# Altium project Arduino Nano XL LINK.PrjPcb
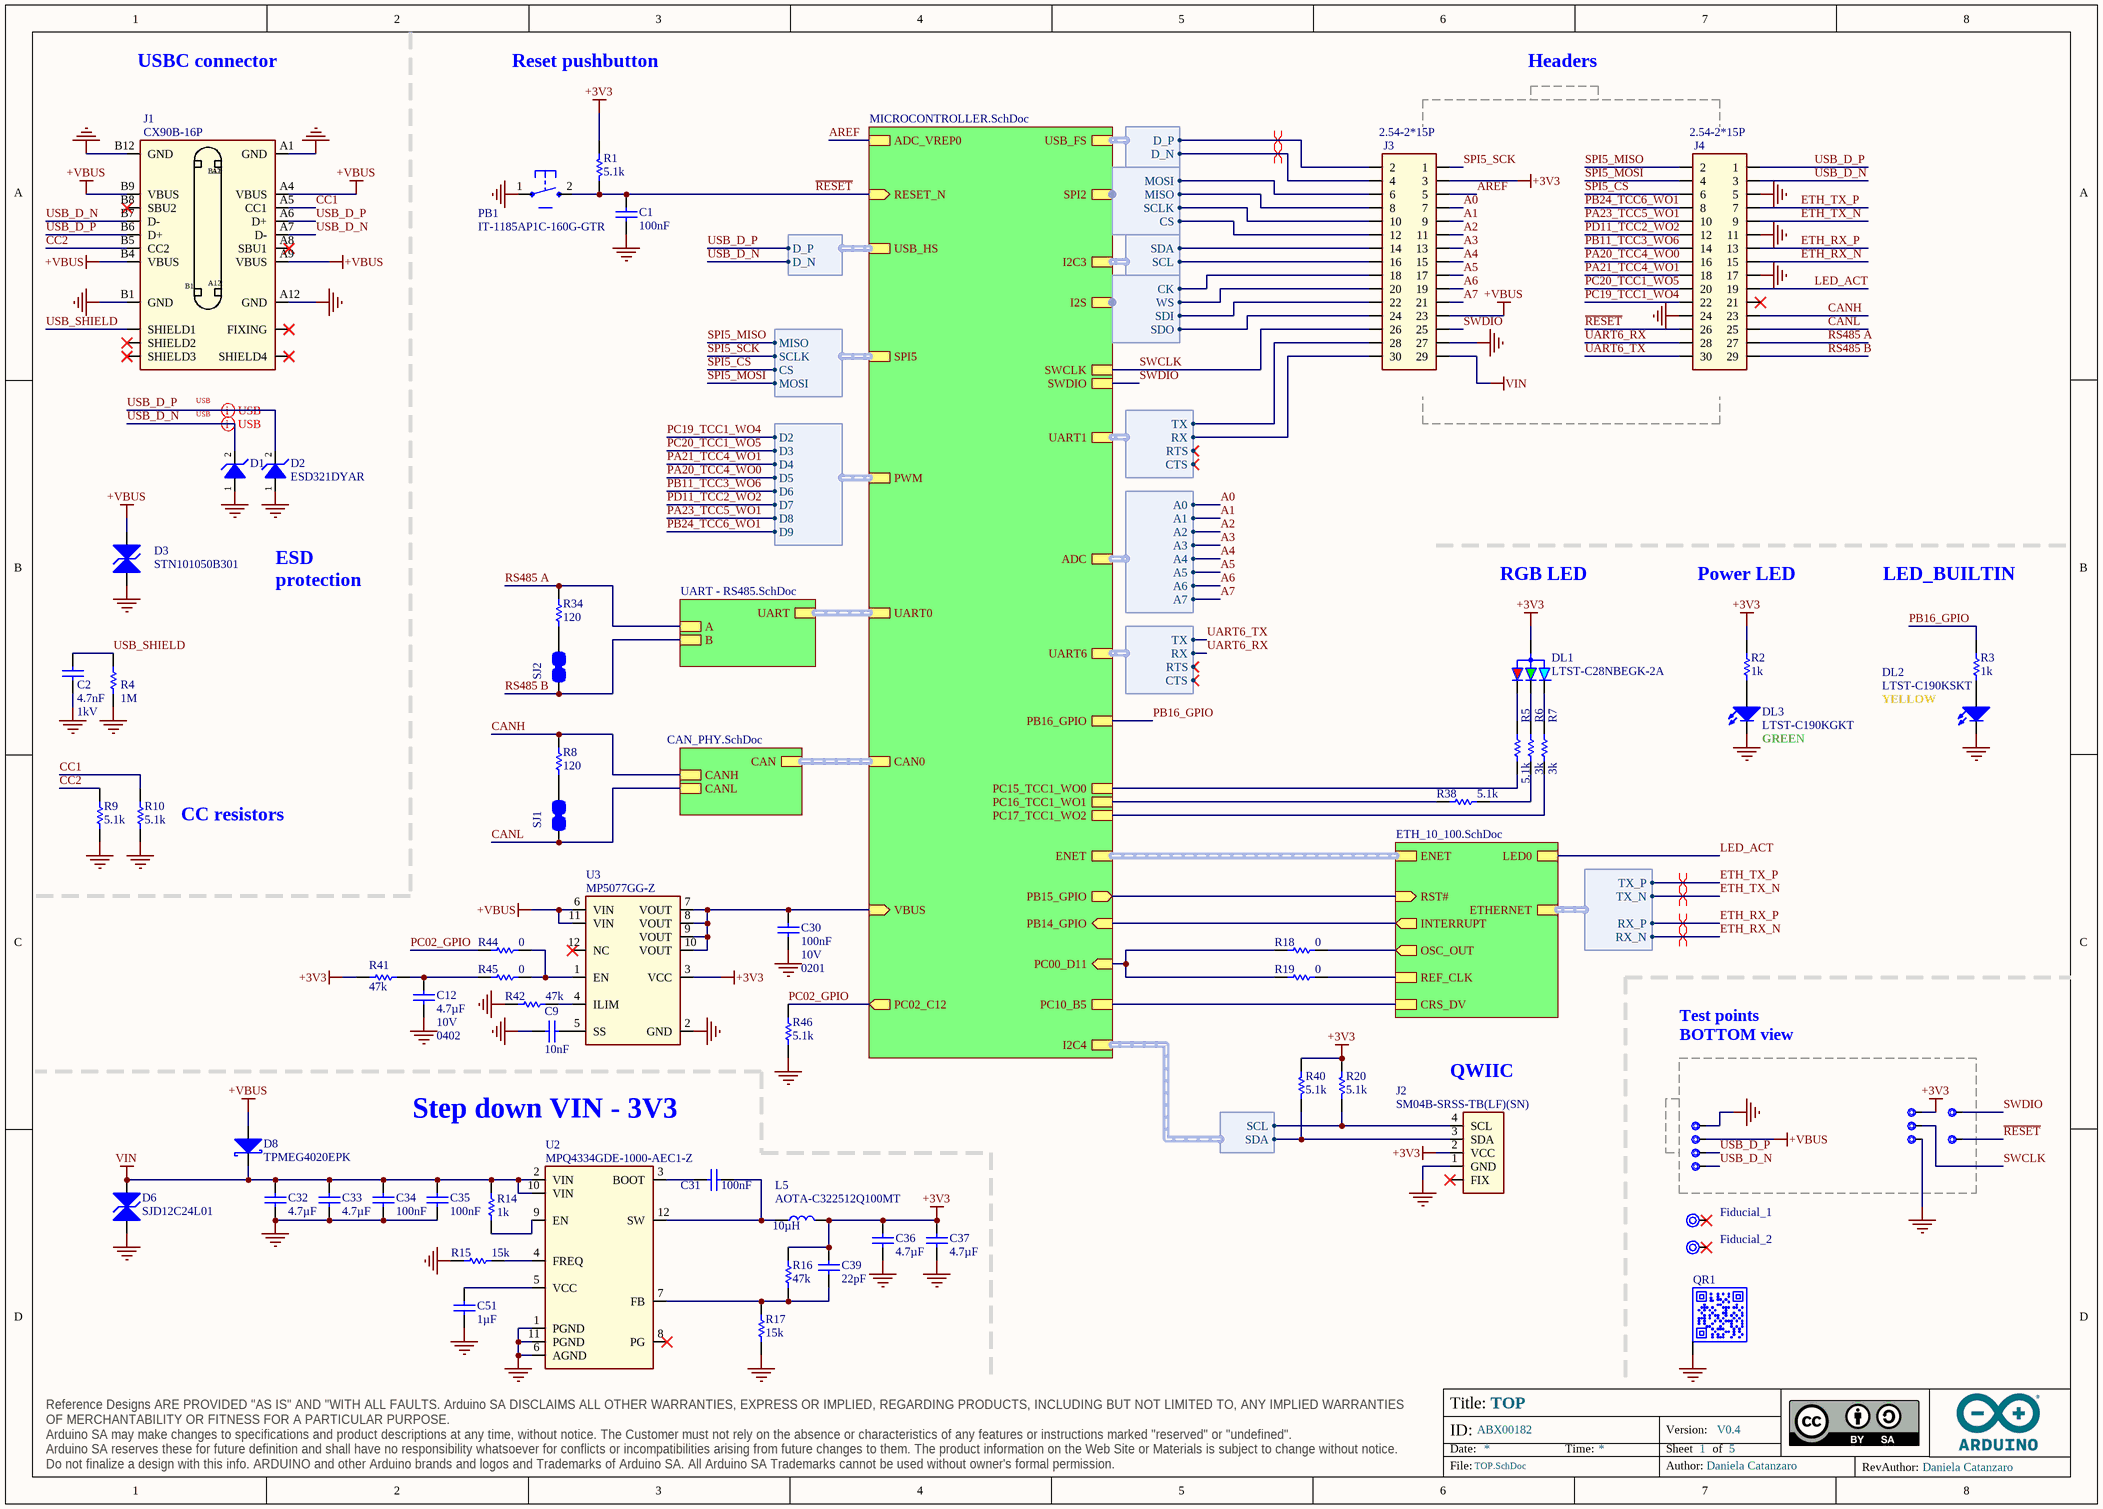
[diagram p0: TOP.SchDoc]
ASSEMBLY_BGA: X; ASSEMBLY_PRESSFIT: _; ASSEMBLY_SMD: X; ASSEMBLY_THT: X; BOARD_CODENAME: Arduino Nano Chandler; BOARD_INFO_AUTHOR: Daniela Catanzaro; BOARD_INFO_AUTHOR_REV: Daniela Catanzaro; BOARD_INFO_Er: _; BOARD_INFO_FLEX: _; BOARD_INFO_FR4: X; BOARD_INFO_FR4_HTG: _; BOARD_INFO_IPC1: _; BOARD_INFO_IPC2: X; BOARD_INFO_IPC3: _; BOARD_INFO_IPC_NA: X; BOARD_INFO_NUMBER_OF_LAYERS: 6; BOARD_INFO_PCB_SIZE: 43.18mm x 22.86mm; BOARD_INFO_POLYMIDE: _; BOARD_INFO_RIGID: X; BOARD_INFO_RIGID/FLEX: _; BOARD_INFO_TBD: _; BOARD_INFO_THICKNESS: 1.6mm; BOARD_OFFICIALNAME: Arduino Nano XL Link; DRILLS_BLIND: X; DRILLS_BURIED: _; DRILLS_COPPER_FILLING: _; DRILLS_FULL: X; DRILLS_LASER: _; DRILLS_PRESSFIT: _; DRILLS_RESIN_FILLING: _; DRILLS_SLOT: _; DRILLS_SOLDER_FILLING: X; FINISH_ADJUSTMENTS: _; FINISH_EDGE_PLATING: _; FINISH_ENIG: X; FINISH_HAL: _; FINISH_HAL_LF: _; FINISH_NI/AU: _; FINISH_SILK_BOTTOM: X; FINISH_SILK_COLOR: WHITE; FINISH_SILK_TOP: X; FINISH_SN/PB: _; FINISH_SOLDERMASK_BOTTOM: X; FINISH_SOLDERMASK_COLOR: BLUE; FINISH_SOLDERMASK_PEELABLE_BOTTOM: _; FINISH_SOLDERMASK_PEELABLE_COLOR: _; FINISH_SOLDERMASK_PEELABLE_TOP: _; FINISH_SOLDERMASK_TOP: X; FINISH_TABS: _; FINISH_TBD: _; INSULATION_MIN_INNER: 0.127mm; INSULATION_MIN_OUTER: 0.127mm; PANEL_MILLING: X; PANEL_NOT_REQUESTED: _; PANEL_NUMBER_OF_FIGURES: 16; PANEL_PROVIDED: X; PANEL_REQUESTED: _; PANEL_SCORING: X; PANEL_SIZE: 213mm x 132mm; PANEL_TABS: _; Revision: V0.4; SKU: ABX00182; TRACK_MIN_WIDTH_INNER: 0.127mm; TRACK_MIN_WIDTH_OUTER: 0.127mm; Version: V0.4; VIA_1: _; VIA_1_HOLE_MM: _; VIA_1_PAD_MM: _; VIA_2: _; VIA_2_HOLE_MM: _; VIA_2_PAD_MM: _; VIA_3: _; VIA_3_HOLE_MM: _; VIA_3_PAD_MM: _; VIA_4: _; VIA_4_HOLE_MM: _; VIA_4_PAD_MM: _; VIA_5: _; VIA_5_HOLE_MM: _; VIA_5_PAD_MM: _; VIA_BLIND_HOLE_MM: 0.1; VIA_BLIND_PAD_MM: 0.2; VIA_THROUGH: X; VIA_THROUGH_HOLE_MM: 0.2; VIA_THROUGH_PAD_MM: 0.4
5 sheets, 127 parts. Net scope: hierarchical (ports join the sheet entries above them; power ports are global).
Board files: PCB.PcbDoc, PANEL.PcbDoc
Sheets:
  TOP.SchDoc
    U_MICROCONTROLLER = MICROCONTROLLER.SchDoc
    U_CAN_PHY = CAN_PHY.SchDoc
    U_ETH_10_100 = ETH_10_100.SchDoc
    U_UART - RS485 = UART - RS485.SchDoc

## Sheet TOP.SchDoc: TOP
size A3; Author: Daniela Catanzaro; DocumentNumber: ABX00182; Revision: V0.1; SheetNumber: 1; SheetTotal: 5; RevAuthor: Daniela Catanzaro

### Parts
1  Test point 1.00mm  [TP-1.00MM]  (value not drawn)  (no BOM)
C1  value 100nF  [CAP-0201]  (hidden comment: CL03A104KP3NNNC)
C2  value 4.7nF  Voltage: 1kV  [CAP-0805]  (hidden comment: FV21X472K102ECG)
C9  value 10nF  [CAP-0201]  (hidden comment: CL03B103KP3NNND)
C12  value 4.7µF  Voltage: 10V  Case Code (Imperial): 0402  [CAP-0402]  (hidden comment: CC0402KRX5R6BB475)
C30  value 100nF  Voltage: 10V  Case Code (Imperial): 0201  [CAP-0201]  (hidden comment: CL03A104KP3NNNC)
C31  value 100nF  [CAP-0402]  (hidden comment: GRM155R61H104KE19D)
C32  value 4.7µF  [CAP-0603]  (hidden comment: GRM188R6YA475KE15D)
C33  value 4.7µF  [CAP-0603]  (hidden comment: GRM188R6YA475KE15D)
C34  value 100nF  [CAP-0402]  (hidden comment: GRM155R61H104KE19D)
C35  value 100nF  [CAP-0402]  (hidden comment: GRM155R61H104KE19D)
C36  value 4.7µF  [CAP-0402]  (hidden comment: CC0402KRX5R6BB475)
C37  value 4.7µF  [CAP-0402]  (hidden comment: CC0402KRX5R6BB475)
C39  value 22pF  [CAP-0201]  (hidden comment: CC0201JPNPO8BN220)
C51  value 1µF  [CAP-0402]  (hidden comment: C1005X5R1E105K050BC)
D1  ESD321DYAR  [ESD321DYAR]  (value not drawn)
D2  ESD321DYAR  [ESD321DYAR]
D3  STN101050B301  [X1-DFN1006-2]
D6  SJD12C24L01  [SOD123W_BIDIR]
D8  TPMEG4020EPK  [DFN1608-2 TPMEG4020EPK]
D+1  Test point 1.00mm  [TP-1.00MM]  (value not drawn)  (no BOM)
D-1  Test point 1.00mm  [TP-1.00MM]  (value not drawn)  (no BOM)
DL1  LTST-C28NBEGK-2A  [SMLP34RGB2W]
DL2  LTST-C190KSKT  [LEDC1608X80N-AK]
DL3  LTST-C190KGKT  [LEDC1608X80N-AK]
Fiducial_1  Fiducial mark 1mm with 2mm solder  [Fiducial mark 1mm with circle-Footprint-1]  (value not drawn)  (no BOM)
Fiducial_2  Fiducial mark 1mm with 2mm solder  [Fiducial mark 1mm with circle-Footprint-1]  (value not drawn)  (no BOM)
GND1  Test point 1.00mm  [TP-1.00MM]  (value not drawn)  (no BOM)
GND2  Test point 1.00mm  [TP-1.00MM]  (value not drawn)  (no BOM)
GPIO1  Test point 1.00mm  [TP-1.00MM]  (value not drawn)  (no BOM)
J1  CX90B-16P  [CX90B-16P-Footprint-1]
J2  SM04B-SRSS-TB(LF)(SN)  [SM04B-SRSS-TB(LF)(SN)-Footprint-1]
J3  2.54-2*15P  [PIN HEADER MALE 2.54mm VERT. 2x15POS]
J4  2.54-2*15P  [PIN HEADER MALE 2.54mm VERT. 2x15POS]
L5  AOTA-C322512Q100MT  Inductance: 10µH  [3225 IND]
NC1  Test point 1.00mm  [TP-1.00MM]  (value not drawn)  (no BOM)
NC2  Test point 1.00mm  [TP-1.00MM]  (value not drawn)  (no BOM)
PB1  IT-1185AP1C-160G-GTR  [C&K_PTS820_NO_HOLES-1]
QR1  QR CODE 4x4mm  [QR CODE 4x4mm]  (value not drawn)  (no BOM)
R1  value 5.1k  [RES-0201]  (hidden comment: RC0201FR-075K1L)
R2  value 1k  [RES-0201]  (hidden comment: RC0201FR-071KL)
R3  value 1k  [RES-0201]  (hidden comment: RC0201FR-071KL)
R4  value 1M  [RES-0402]  (hidden comment: CRCW04021M00FKED)
R5  value 5.1k  [RES-0201]  (hidden comment: RC0201FR-075K1L)
R6  value 3k  [RES-0201]  (hidden comment: RC0201FR-073KL)
R7  value 3k  [RES-0201]  (hidden comment: RC0201FR-073KL)
R8  value 120  [RES-0201]  (hidden comment: RC0201FR-07120RL)
R9  value 5.1k  [RES-0201]  (hidden comment: RC0201FR-075K1L)
R10  value 5.1k  [RES-0201]  (hidden comment: RC0201FR-075K1L)
R14  value 1k  [RES-0201]  (hidden comment: RC0201FR-071KL)
R15  value 15k  [RES-0201]  (hidden comment: CRCW020115K0FKED)
R16  value 47k  [RES-0201]  (hidden comment: CRCW020147K0FNEDAT)
R17  value 15k  [RES-0201]  (hidden comment: CRCW020115K0FKED)
R18  value 0  [RES-0201]  (hidden comment: CRCW02010000Z0ED)
R19  value 0  [RES-0201]  (hidden comment: CRCW02010000Z0ED)
R20  value 5.1k  [RES-0201]  (hidden comment: RC0201FR-075K1L)
R34  value 120  [RES-0201]  (hidden comment: RC0201FR-07120RL)
R38  value 5.1k  [RES-0201]  (hidden comment: RC0201FR-075K1L)
R40  value 5.1k  [RES-0201]  (hidden comment: RC0201FR-075K1L)
R41  value 47k  [RES-0201]  (hidden comment: CRCW020147K0FNEDAT)
R42  value 47k  [RES-0201]  (hidden comment: CRCW020147K0FNEDAT)
R44  value 0  [RES-0201]  (hidden comment: CRCW02010000Z0ED)
R45  value 0  [RES-0201]  (hidden comment: CRCW02010000Z0ED)
R46  value 5.1k  [RES-0201]  (hidden comment: RC0201FR-075K1L)
SJ1  SOLDER JUMPER CLOSED 0603  [SJ 0603 CLOSED]  (value not drawn)  (no BOM)
SJ2  SOLDER JUMPER CLOSED 0603  [SJ 0603 CLOSED]  (value not drawn)  (no BOM)
TP_VUSB1  Test point 1.00mm  [TP-1.00MM]  (value not drawn)  (no BOM)
U2  MPQ4334GDE-1000-AEC1-Z  [MPQ4334GDE-1000-AEC1-Z]
U3  MP5077GG-Z  [MPS QFN12 2x2mm pitch 0.4mm]

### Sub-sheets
U_CAN_PHY = CAN_PHY.SchDoc: CAN (harness CAN_3V3), CANH, CANL
U_ETH_10_100 = ETH_10_100.SchDoc: LED0, ETHERNET (harness ETH), ENET (harness ENET), RST# (in), INTERRUPT (out), OSC_OUT (out), REF_CLK, CRS_DV
U_MICROCONTROLLER = MICROCONTROLLER.SchDoc: RESET_N (in), USB_HS (harness USB), SPI5 (harness SPI), ENET (harness ENET), CAN0 (harness CAN_3V3), SPI2 (harness SPI), UART1 (harness UART), I2S (harness I2S), ADC (harness ANALOG), ADC_VREP0, PWM (harness PWM), I2C3 (harness I2C), USB_FS (harness USB), UART6 (harness UART), SWDIO, SWCLK, PB14_GPIO (in), PB15_GPIO (out), PC15_TCC1_WO0, PC16_TCC1_WO1, PC17_TCC1_WO2, PB16_GPIO, PC00_D11 (in), PC10_B5, UART0 (harness UART), I2C4 (harness I2C), VBUS (in), PC02_C12 (out)
U_UART - RS485 = UART - RS485.SchDoc: UART (harness UART), A, B

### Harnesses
ANALOG: A0, A1, A2, A3, A4, A5, A6, A7
USB: D_P, D_N
I2C: SDA, SCL
SPI: CS, MOSI, SCLK, MISO
UART: CTS, RX, RTS, TX
I2S: SDO, WS, SDI, CK
PWM: D2, D3, D4, D5, D6, D7, D8, D9
ETH: TX_N, TX_P, RX_N, RX_P

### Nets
+3V3: 1.X C36.2 C37.2 C39.2 DL1.1(ANODE) J2.2(VCC) J3.3 L5.2 R1.2 R2.2 R16.2 R20.2 R40.2 R41.2 U3.3(VCC)
+VBUS: D3.1(A1) D8.A J1.A4(VBUS) J1.A9(VBUS) J1.B4(VBUS) J1.B9(VBUS) J3.23 TP_VUSB1.X U3.6(VIN) U3.11(VIN)
GND: C1.1 C2.1 C9.2 C12.1 C30.1 C32.1 C33.1 C34.1 C35.1 C36.1 C37.1 C51.1 D1.1 D2.1 D3.2(A2) D6.1(A1) DL2.C DL3.C GND1.X GND2.X J1.A1(GND) J1.A12(GND) J1.B1(GND) J1.B12(GND) J2.1(GND) J3.27 J4.5 J4.11 J4.17 J4.24 PB1.1 QR1.PAD R4.1 R9.1 R10.1 R15.2 R17.1 R42.2 R46.2 U2.1(PGND) U2.6(AGND) U2.11(PGND) U3.2(GND)
VIN: C32.2 C33.2 C34.2 C35.2 D6.2(A2) D8.C J3.29 R14.1 U2.2(VIN) U2.10(VIN)
A0: J3.7 ; sheet U_MICROCONTROLLER/ADC.A0
A1: J3.9 ; sheet U_MICROCONTROLLER/ADC.A1
A2: J3.11 ; sheet U_MICROCONTROLLER/ADC.A2
A3: J3.13 ; sheet U_MICROCONTROLLER/ADC.A3
A4: J3.15 ; sheet U_MICROCONTROLLER/ADC.A4
A5: J3.17 ; sheet U_MICROCONTROLLER/ADC.A5
A6: J3.19 ; sheet U_MICROCONTROLLER/ADC.A6
A7: J3.21 ; sheet U_MICROCONTROLLER/ADC.A7
AREF: J3.5 ; sheet U_MICROCONTROLLER/ADC_VREP0
CANH: J4.23 R8.2 ; sheet U_CAN_PHY/CANH
CANL: J4.25 SJ1.1 ; sheet U_CAN_PHY/CANL
CC1: J1.A5(CC1) R10.2  [project net CC1_1]
CC2: J1.B5(CC2) R9.2  [project net CC2_1]
ETH_RX_N: J4.15 ; sheet U_ETH_10_100/ETHERNET.RX_N
ETH_RX_P: J4.13 ; sheet U_ETH_10_100/ETHERNET.RX_P
ETH_TX_N: J4.9 ; sheet U_ETH_10_100/ETHERNET.TX_N
ETH_TX_P: J4.7 ; sheet U_ETH_10_100/ETHERNET.TX_P
INTRP: sheet U_MICROCONTROLLER/PB14_GPIO, sheet U_ETH_10_100/INTERRUPT
LED_ACT: J4.19 ; sheet U_ETH_10_100/LED0  [project net ANEN_SPEED]
PA20_TCC4_WO0: J4.16 ; sheet U_MICROCONTROLLER/PWM.D5
PA21_TCC4_WO1: J4.18 ; sheet U_MICROCONTROLLER/PWM.D4
PA23_TCC5_WO1: J4.10 ; sheet U_MICROCONTROLLER/PWM.D8
PB11_TCC3_WO6: J4.14 ; sheet U_MICROCONTROLLER/PWM.D6
PB16_GPIO: R3.2 ; sheet U_MICROCONTROLLER/PB16_GPIO
PB24_TCC6_WO1: J4.8 ; sheet U_MICROCONTROLLER/PWM.D9
PC02_GPIO: R44.2 R46.1 ; sheet U_MICROCONTROLLER/PC02_C12
PC19_TCC1_WO4: J4.22 ; sheet U_MICROCONTROLLER/PWM.D2
PC20_TCC1_WO5: J4.20 ; sheet U_MICROCONTROLLER/PWM.D3
PD11_TCC2_WO2: J4.12 ; sheet U_MICROCONTROLLER/PWM.D7
PHYAD_1:0: sheet U_MICROCONTROLLER/PC10_B5, sheet U_ETH_10_100/CRS_DV
PHYAD_2: R19.1 ; sheet U_ETH_10_100/REF_CLK
~{RESET}: C1.2 J4.26 NC2.X PB1.2 R1.1 ; sheet U_MICROCONTROLLER/RESET_N
RS485 A: J4.27 R34.2 ; sheet U_UART - RS485/A
RS485 B: J4.29 SJ2.1 ; sheet U_UART - RS485/B
RST#: sheet U_MICROCONTROLLER/PB15_GPIO, sheet U_ETH_10_100/RST#
SPI2_CS: J3.12 ; sheet U_MICROCONTROLLER/SPI2.CS
SPI5_CS: J4.6 ; sheet U_MICROCONTROLLER/SPI5.CS
SPI5_MISO: J4.2 ; sheet U_MICROCONTROLLER/SPI5.MISO
SPI5_MOSI: J4.4 ; sheet U_MICROCONTROLLER/SPI5.MOSI
SPI5_SCK: J3.1 ; sheet U_MICROCONTROLLER/SPI5.SCLK
SWCLK: GPIO1.X J3.26 ; sheet U_MICROCONTROLLER/SWCLK
SWDIO: J3.25 NC1.X ; sheet U_MICROCONTROLLER/SWDIO
UART6_RX: J4.28 ; sheet U_MICROCONTROLLER/UART6.RX
UART6_TX: J4.30 ; sheet U_MICROCONTROLLER/UART6.TX
USB_D_N: D1.2 D-1.X J1.A7(D-) J1.B7(D-) J4.3 ; sheet U_MICROCONTROLLER/USB_HS.D_N
USB_D_P: D2.2 D+1.X J1.A6(D+) J1.B6(D+) J4.1 ; sheet U_MICROCONTROLLER/USB_HS.D_P
USB_SHIELD: C2.2 J1.SHIELD1 R4.2  [project net USB_SHIELD_1]
USBFS_D_N: J3.4 ; sheet U_MICROCONTROLLER/USB_FS.D_N
USBFS_D_P: J3.2 ; sheet U_MICROCONTROLLER/USB_FS.D_P
NetC9_1: C9.1 U3.5(SS)
NetC12_2: C12.2 R41.1 R45.2
NetC30_2: C30.2 U3.7(VOUT) U3.8(VOUT) U3.9(VOUT) U3.10(VOUT) ; sheet U_MICROCONTROLLER/VBUS
NetC31_1: C31.1 L5.1 U2.12(SW)
NetC31_2: C31.2 U2.3(BOOT)
NetC39_1: C39.1 R16.1 R17.2 U2.7(FB)
NetC51_2: C51.2 U2.5(VCC)
NetDL1_2: DL1.2(RED_C) R5.2
NetDL1_3: DL1.3(BLUE_C) R7.2
NetDL1_4: DL1.4(GREEN_C) R6.2
NetDL2_A: DL2.A R3.1
NetDL3_A: DL3.A R2.1
NetJ2_3: J2.3(SDA) R40.1 ; sheet U_MICROCONTROLLER/I2C4.SDA
NetJ2_4: J2.4(SCL) R20.1 ; sheet U_MICROCONTROLLER/I2C4.SCL
NetJ3_6: J3.6 ; sheet U_MICROCONTROLLER/SPI2.MOSI
NetJ3_8: J3.8 ; sheet U_MICROCONTROLLER/SPI2.MISO
NetJ3_10: J3.10 ; sheet U_MICROCONTROLLER/SPI2.SCLK
NetJ3_14: J3.14 ; sheet U_MICROCONTROLLER/I2C3.SDA
NetJ3_16: J3.16 ; sheet U_MICROCONTROLLER/I2C3.SCL
NetJ3_18: J3.18 ; sheet U_MICROCONTROLLER/I2S.CK
NetJ3_20: J3.20 ; sheet U_MICROCONTROLLER/I2S.WS
NetJ3_22: J3.22 ; sheet U_MICROCONTROLLER/I2S.SDI
NetJ3_24: J3.24 ; sheet U_MICROCONTROLLER/I2S.SDO
NetJ3_28: J3.28 ; sheet U_MICROCONTROLLER/UART1.TX
NetJ3_30: J3.30 ; sheet U_MICROCONTROLLER/UART1.RX
NetR5_1: R5.1 ; sheet U_MICROCONTROLLER/PC15_TCC1_WO0
NetR6_1: R6.1 R38.1
NetR7_1: R7.1 ; sheet U_MICROCONTROLLER/PC17_TCC1_WO2
NetR8_1: R8.1 SJ1.2
NetR14_2: R14.2 U2.9(EN)
NetR15_1: R15.1 U2.4(FREQ)
NetR18_1: R18.1 ; sheet U_ETH_10_100/OSC_OUT
NetR18_2: R18.2 R19.2 ; sheet U_MICROCONTROLLER/PC00_D11
NetR34_1: R34.1 SJ2.2
NetR38_2: R38.2 ; sheet U_MICROCONTROLLER/PC16_TCC1_WO1
NetR42_1: R42.1 U3.4(ILIM)
NetR44_1: R44.1 R45.1 U3.1(EN)

Not connected (* = marked no-connect by the designer): Fiducial_1 1*; Fiducial_2 1*; J1 A8(SBU1)* B8(SBU2)* FIXING* SHIELD2* SHIELD3* SHIELD4*; J2 FIX*; J4 21*; U2 8(PG)*; U3 12(NC)*

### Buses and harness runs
harness sheet U_CAN_PHY/CAN = sheet U_MICROCONTROLLER/CAN0
harness sheet U_ETH_10_100/ENET = sheet U_MICROCONTROLLER/ENET
harness sheet U_MICROCONTROLLER/UART0 = sheet U_UART - RS485/UART

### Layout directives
differential pair; differential pair class USB: USB_D_N, USB_D_P
differential pair; differential pair class USBC_FS: USBFS_D_N, USBFS_D_P
differential pair; differential pair class ETH: ETH_RX_N, ETH_RX_P, ETH_TX_N, ETH_TX_P

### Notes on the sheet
- USBC connector
- Reset pushbutton
- Headers
- RGB LED
- Power LED
- LED_BUILTIN
- ESD
  protection
- YELLOW
- (near DL3) GREEN
- (near R10) CC resistors
- Test points BOTTOM view
- Step down VIN - 3V3
- (near J2) QWIIC

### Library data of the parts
1 D+1 D-1 GND1 GND2 GPIO1 NC1 NC2 TP_VUSB1 = UT0013-A.6: Manufacturer: This is not a component
C1 C30 = C0113-A.8: CAP CHIP 0201 100nF 10% 10V X5R; Manufacturer: Samsung Electro-Mechanics; Code Arduino: C0113
C2 = C0059-A.16: CAP CHIP 0805 4.7nF 10% 1000V X7R; Manufacturer: PSA Shenzen; Code Arduino: 0689
C9 = C0205-A.3: CAP CHIP 0201 10nF 10% 10V X7R; Manufacturer: Samsung; Code Arduino: C0205
C12 C36 C37 = C0195-A.3: CAP CHIP 0402 4.7uF 10% 10V X5R; Manufacturer: YAGEO; Code Arduino: C0195
C31 C34 C35 = C0015-A.16: CAP CHIP 0402 100nF 10% 50V X5R; Manufacturer: Murata; Code Arduino: A5141
C32 C33 = C0055-A.16: CAP CHIP 0603 4.7uF 10% 35V X5R; Manufacturer: Murata; Code Arduino: 0458
C39 = C0115-A.8: CAP CHIP 0201 22pF 5% 25V C0G; Manufacturer: Yageo; Code Arduino: C0115
C51 = C0177-A.4: CAP CHIP 0402 1uF 10% 25V X5R; Manufacturer: TDK; Code Arduino: C0177
D1 D2 = P0022-5: TVS 1CH, 30kV, USB 2.0 ETH 10/100/1000, 0-3.6V, 0.9pF, IEC61000-4-5 peak current 80A surge 40W 6A, DC breakdown min 4.5V, SOD523 1.6x0.8mm; Manufacturer: Texas Instruments; Code Arduino: P0022
D3 = D0095-2: TVS BIDIRECTIONAL SMD Vr = 5V, Vbr min =  5.5V, 300W, DFN1006-2; Manufacturer: Eaton Electronics; Ireverse max: 1µA; Vforward max: 0V; Code Arduino: D0095
D6 = D0106-4: TVS BIDIRECTIONAL SMD Vr = 24V, Vbr min =  26.7V, Vcl = 38.9V, Ileakage = 1uA, 200W, SOD-123; Manufacturer: YAGEO; Code Arduino: D0106; V(BR) min: 26.7; V(RWM) max: 24; Ireverse max: 1µA; Vforward max: 0V
D8 = D0105-1: DIODE SCHOTTKY SMD 2A 40V DFN1608-2; Manufacturer: TECH PUBLIC; Code Arduino: D0105; Vforward max: 550mV; Power max: 415mW
DL1 = L0014-A.13: LED RGB DIFFUSED PICOLED SMD; Manufacturer: Liteon; Code Arduino: A5469; Lens Style: Rectangular; Forward Voltage: 3V; Luminous Intensity: 45mcd; Lens Color: White; Dominant Wavelength: 470nm; Forward Current: 20mA; Test Current: 5mA
DL2 = L0008-A.6: LED SMD 0603 GIA588   8mcd 120^; Manufacturer: Liteon; Code Arduino: 2243
DL3 = L0009-A.6: LED SMD 0603 GREEN/568 15mcd 120^; Manufacturer: Liteon; Code Arduino: 2204
Fiducial_1 Fiducial_2 = UT0024-A.6
J1 = J0272-A.3: CONN RCPT USB3.1 TYPEC 16POS SMD; Manufacturer: Hirose; Code Arduino: J0272
J2 = J0005-A.3: CONN JST SH 1mm 4POS HORIZONTAL TIN QWIIC; Code Arduino: J0005
J3 J4 = J0592-A.5: HEADER TH 2.54mm VERT. 2x015POS MALE 6mm pin height; Manufacturer: BOOMELE; Code Arduino: J0592
L5 = I0131-A.1: IND FIXED 10uH 210mR Idc:1.8A Isat:2.3A 3.2 x 2.5 x 1.2mm; Manufacturer: ABRACON; Resonant frequency: 1MHz; Tolerance: 20%; ISAT: 2.3A; Code Arduino: I0131; IRMS: 1.8A
PB1 = B0001-A.7: PUSHBUTTON WHITE NO ANCHORS; Manufacturer: Switronic; Code Arduino: 0173
QR1 = QR-0001-A.5: QR CODE 4x4mm on layer 34 (This is not a component); Code Arduino: QRCODE_4x4mm
R1 R5 R20 R38 R40 R46 = R0169-A.26: RES CHIP 0201 5k1 1% 1/20W; Manufacturer: Yageo; Code Arduino: R0169; Power: 50mW; Temperature coefficient: 200ppm
R2 R3 = R0195-A.23: RES CHIP 0201 1k 1% 1/20W; Manufacturer: Yageo; Code Arduino: R0195; Power: 50mW; Temperature coefficient: 200ppm
R4 = R0058-A.25: RES CHIP 0402 1M 1% 1/16W; Manufacturer: Vishay; Power: 62.5mW; Code Arduino: 0139; Temperature coefficient: 100ppm
R6 R7 = R0416-A.2: RES CHIP 0201 3k 1% 1/20W; Manufacturer: YAGEO; Code Arduino: R0416; Power: 50mW; Temperature Coefficient: 200ppm
R8 R34 = R0306-A.2: RES CHIP 0201 120R 1% 1/20W; Manufacturer: YAGEO; Code Arduino: R0306; Power: 50mW; Temperature Coefficient: 200ppm
R9 R10 = R0169-A.26: RES CHIP 0201 5k1 1% 1/20W; Manufacturer: Yageo; Power: 50mW; Code Arduino: R0169; Temperature coefficient: 200ppm
R14 = R0195-A.23: RES CHIP 0201 1k 1% 1/20W; Manufacturer: Yageo; Temperature coefficient: 200ppm; Power: 50mW; Code Arduino: R0195
R15 R17 = R0213-A.19: RES CHIP 0201 15k 1% 1/20W; Manufacturer: Vishay; Code Arduino: R0213; Power: 50mW; Temperature coefficient: 100ppm
R16 R41 R42 = R0413-A.2: RES CHIP 0201 47k 1% 1/20W; Manufacturer: Vishay; Code Arduino: R0413; Power: 50mW; Temperature Coefficient: 200ppm
R18 R19 R44 R45 = R0140-A.22: RES CHIP 0201 0R; Manufacturer: Vishay; Temperature coefficient: 0ppm; Code Arduino: R0140; Power: 50mW; Tolerance: 0%
SJ1 SJ2 = UT0039-A.4: Code Arduino: This is not a component
U2 = U0537-A.2: IC BUCK Vin 36V, Vout ADJ, Iout 1A, synchronous 65mR/45mR, 2.5MHz, QFN12 2x3mm; Manufacturer: MPS; Code Arduino: U0537
U3 = U0512-A.2: IC Load Switch Vload 0.5V to 5.5V, 10mR at 5V, max 7A, programmable overcurrent limit, linear ramp control, logic ON 1.7V, VCC 3V to 5.5V, -40 to 125°C, QFN12 2x2mm; Manufacturer: MPS; Code Arduino: U0512

## Sheet MICROCONTROLLER.SchDoc: MICROCONTROLLER
size A3; SheetNumber: 2; SheetTotal: 5
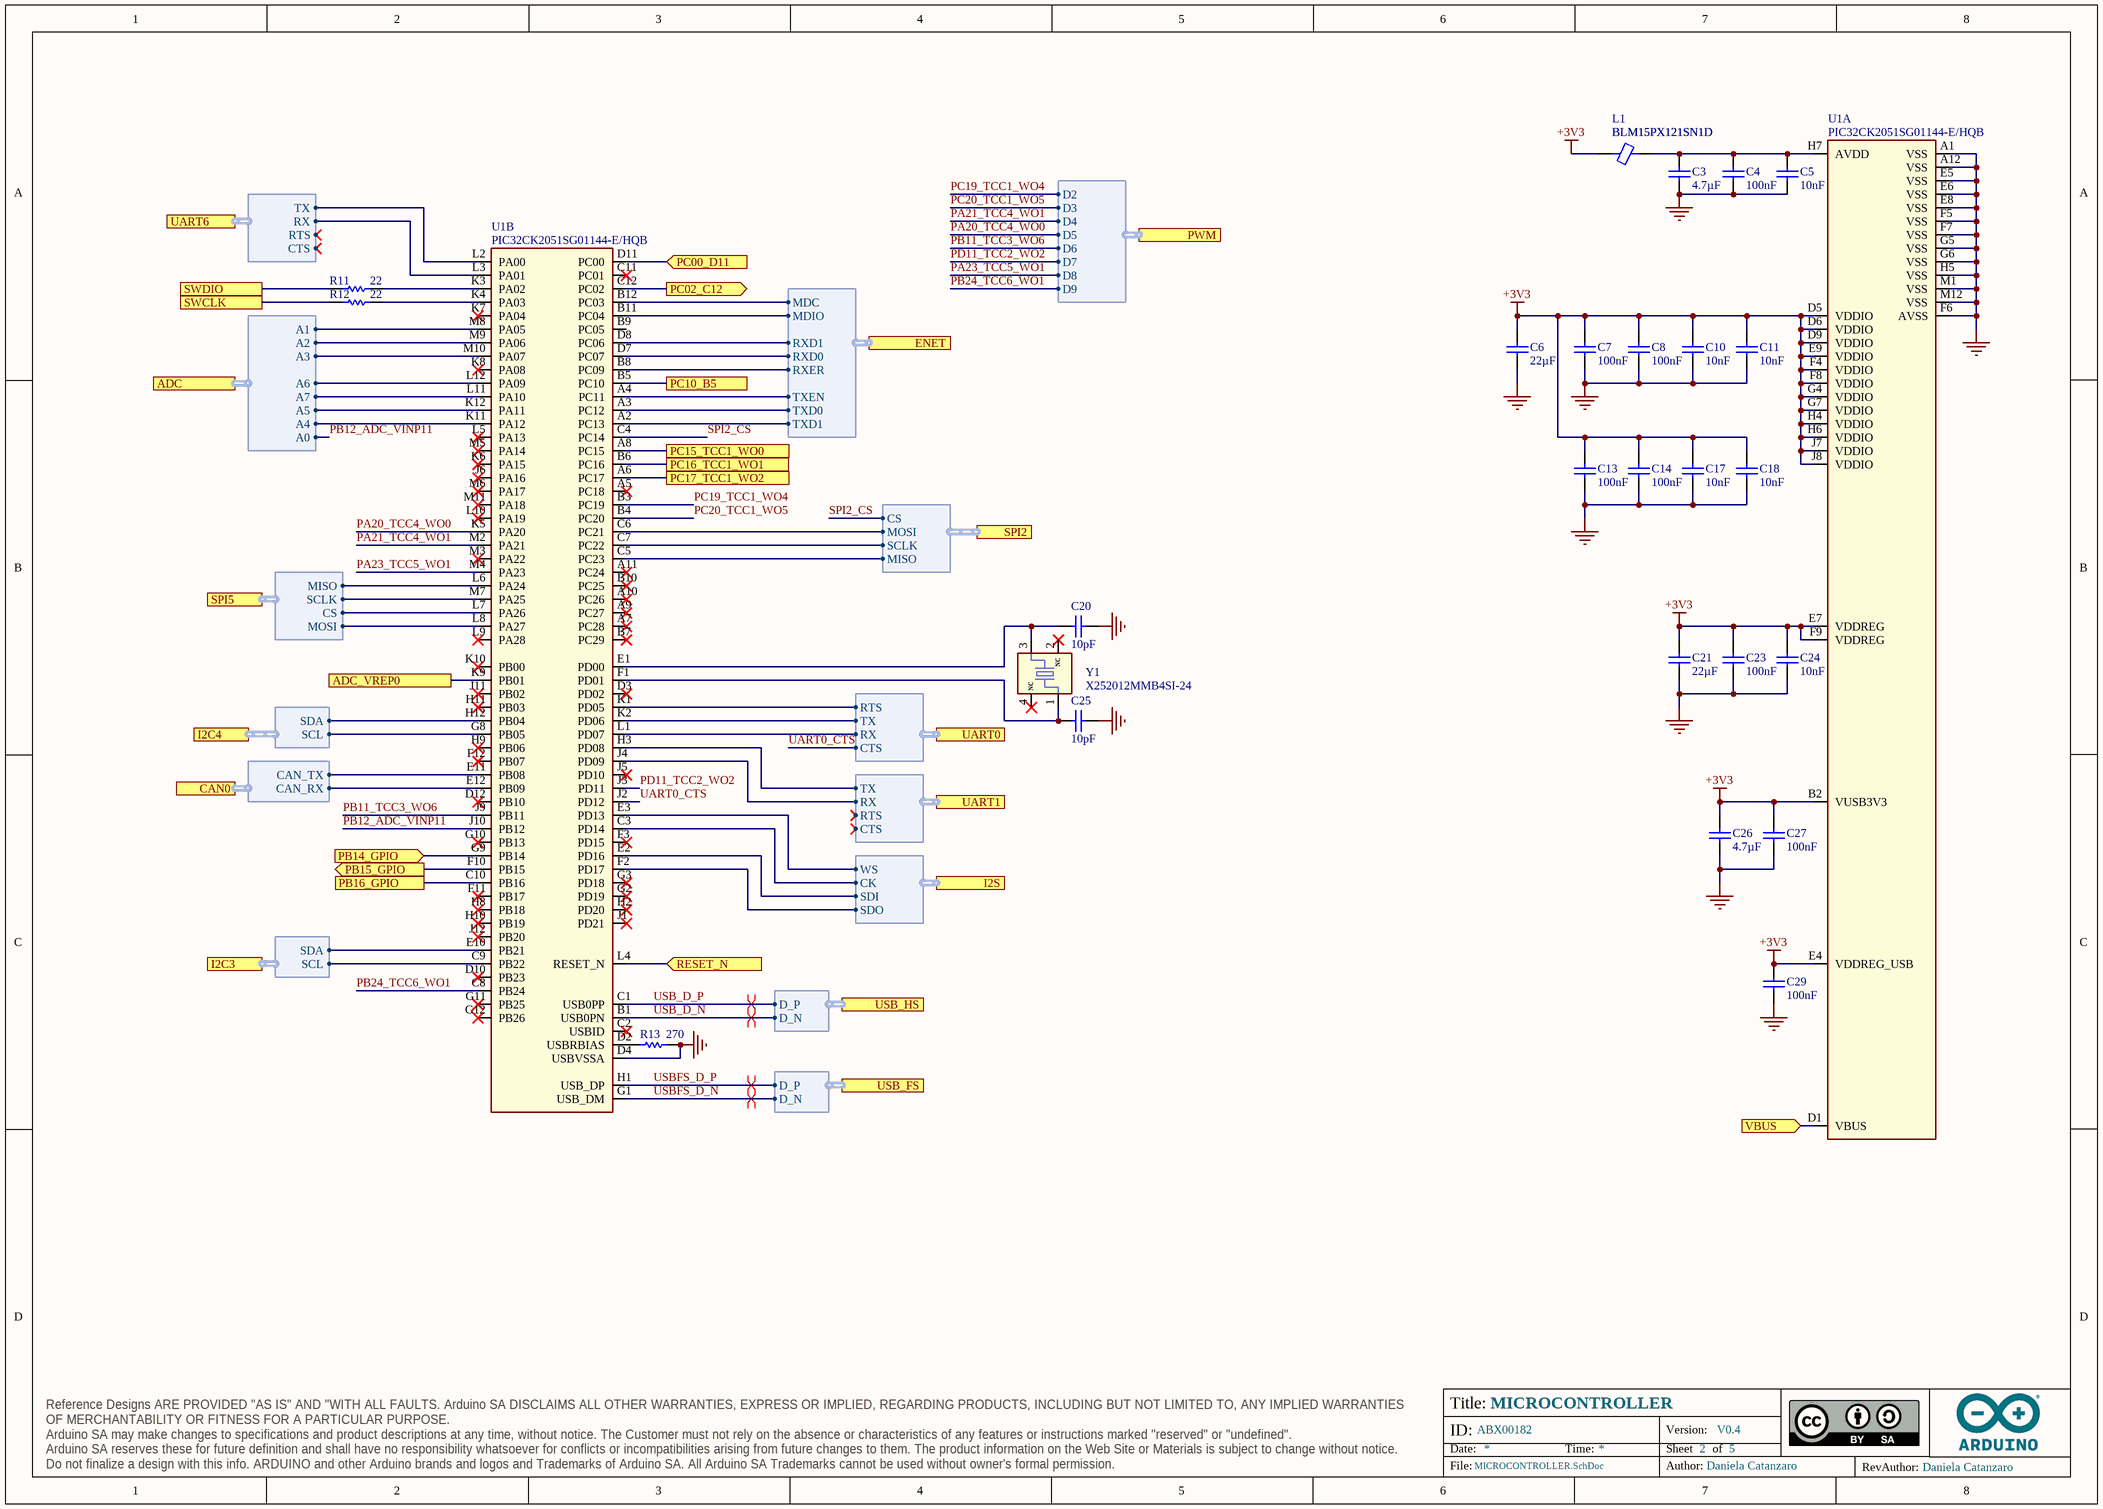
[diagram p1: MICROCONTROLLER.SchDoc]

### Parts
C3  value 4.7µF  [CAP-0402]  (hidden comment: CC0402KRX5R6BB475)
C4  value 100nF  [CAP-0201]  (hidden comment: CL03A104KP3NNNC)
C5  value 10nF  [CAP-0201]  (hidden comment: CL03B103KP3NNND)
C6  value 22µF  [CAP-0402]  (hidden comment: GRM158R60J226ME01D)
C7  value 100nF  [CAP-0201]  (hidden comment: CL03A104KP3NNNC)
C8  value 100nF  [CAP-0201]  (hidden comment: CL03A104KP3NNNC)
C10  value 10nF  [CAP-0201]  (hidden comment: CL03B103KP3NNND)
C11  value 10nF  [CAP-0201]  (hidden comment: CL03B103KP3NNND)
C13  value 100nF  [CAP-0201]  (hidden comment: CL03A104KP3NNNC)
C14  value 100nF  [CAP-0201]  (hidden comment: CL03A104KP3NNNC)
C17  value 10nF  [CAP-0201]  (hidden comment: CL03B103KP3NNND)
C18  value 10nF  [CAP-0201]  (hidden comment: CL03B103KP3NNND)
C20  value 10pF  [CAP-0201]  (hidden comment: CC0201GRNPO9BN100)
C21  value 22µF  [CAP-0402]  (hidden comment: GRM158R60J226ME01D)
C23  value 100nF  [CAP-0201]  (hidden comment: CL03A104KP3NNNC)
C24  value 10nF  [CAP-0201]  (hidden comment: CL03B103KP3NNND)
C25  value 10pF  [CAP-0201]  (hidden comment: CC0201GRNPO9BN100)
C26  value 4.7µF  [CAP-0402]  (hidden comment: CC0402KRX5R6BB475)
C27  value 100nF  [CAP-0201]  (hidden comment: CL03A104KP3NNNC)
C29  value 100nF  [CAP-0201]  (hidden comment: CL03A104KP3NNNC)
L1  BLM15PX121SN1D  [L-0402]
R11  value 22  [RES-0201]  (hidden comment: RC0201FR-0722RL)
R12  value 22  [RES-0201]  (hidden comment: RC0201FR-0722RL)
R13  value 270  [RES-0201]  (hidden comment: RC0201FR-07270RL)
U1  PIC32CK2051SG01144-E/HQB  [TFBGA-144]  (parts A,B of 2)
Y1  X252012MMB4SI-24  [CRYSTAL_2.5x2mm]

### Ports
ADC (harness ANALOG), ADC_VREP0, CAN0 (harness CAN_3V3), ENET (harness ENET), I2C3 (harness I2C), I2C4 (harness I2C), I2S (harness I2S), PB14_GPIO (in), PB15_GPIO (out), PB16_GPIO, PC00_D11 (in), PC02_C12 (out), PC10_B5, PC15_TCC1_WO0, PC16_TCC1_WO1, PC17_TCC1_WO2, PWM (harness PWM), RESET_N (in), SPI2 (harness SPI), SPI5 (harness SPI), SWCLK, SWDIO, UART0 (harness UART), UART1 (harness UART), UART6 (harness UART), USB_FS (harness USB), USB_HS (harness USB), VBUS (in)

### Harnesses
USB: D_P, D_N
SPI: CS, MOSI, SCLK, MISO
ENET: TXEN, TXD0, TXD1, RXD0, RXD1, MDC, MDIO, RXER
CAN_3V3: CAN_TX, CAN_RX
UART: CTS, RX, RTS, TX
I2C: SDA, SCL
I2S: SDO, WS, SDI, CK
ANALOG: A0, A1, A2, A3, A6, A7, A5, A4
PWM: D2, D3, D4, D5, D6, D7, D8, D9

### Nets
+3V3: C6.2 C7.2 C8.2 C10.2 C11.2 C13.2 C14.2 C17.2 C18.2 C21.2 C23.2 C24.2 C26.2 C27.2 C29.2 L1.1 U1.B2(VUSB3V3) U1.D5(VDDIO) U1.D6(VDDIO) U1.D9(VDDIO) U1.E4(VDDREG_USB) U1.E7(VDDREG) U1.E9(VDDIO) U1.F4(VDDIO) U1.F8(VDDIO) U1.F9(VDDREG) U1.G4(VDDIO) U1.G7(VDDIO) U1.H4(VDDIO) U1.H6(VDDIO) U1.J7(VDDIO) U1.J8(VDDIO)
GND: C3.1 C4.1 C5.1 C6.1 C7.1 C8.1 C10.1 C11.1 C13.1 C14.1 C17.1 C18.1 C20.2 C21.1 C23.1 C24.1 C25.2 C26.1 C27.1 C29.1 R13.2 U1.A1(VSS) U1.A12(VSS) U1.D4(USBVSSA) U1.E5(VSS) U1.E6(VSS) U1.E8(VSS) U1.F5(VSS) U1.F6(AVSS) U1.F7(VSS) U1.G5(VSS) U1.G6(VSS) U1.H5(VSS) U1.M1(VSS) U1.M12(VSS)
A1: U1.M8(PA05) ; port ADC.A1
A2: U1.M9(PA06) ; port ADC.A2
A3: U1.M10(PA07) ; port ADC.A3
A4: U1.K11(PA12) ; port ADC.A4
A5: U1.K12(PA11) ; port ADC.A5
A6: U1.L12(PA09) ; port ADC.A6
A7: U1.L11(PA10) ; port ADC.A7
AREF: U1.K9(PB01) ; port ADC_VREP0
INTRP: U1.G9(PB14) ; port PB14_GPIO
MDC: U1.B12(PC03) ; port ENET.MDC
MDIO: U1.B11(PC04) ; port ENET.MDIO
PA20_TCC4_WO0: U1.K5(PA20) ; port PWM.D5
PA21_TCC4_WO1: U1.M2(PA21) ; port PWM.D4
PA23_TCC5_WO1: U1.M4(PA23) ; port PWM.D8
PB11_TCC3_WO6: U1.J9(PB11) ; port PWM.D6
PB12_ADC_VINP11: U1.J10(PB12) ; port ADC.A0  [project net A0]
PB16_GPIO: U1.C10(PB16) ; port PB16_GPIO
PB24_TCC6_WO1: U1.C8(PB24) ; port PWM.D9
PC02_GPIO: U1.C12(PC02) ; port PC02_C12
PC19_TCC1_WO4: U1.B3(PC19) ; port PWM.D2
PC20_TCC1_WO5: U1.B4(PC20) ; port PWM.D3
PD11_TCC2_WO2: U1.J3(PD11) ; port PWM.D7
PHYAD_1:0: U1.B5(PC10) ; port PC10_B5
~{RESET}: U1.L4(RESET_N) ; port RESET_N
RST#: U1.F10(PB15) ; port PB15_GPIO
RXD0: U1.D7(PC07) ; port ENET.RXD0
RXD1: U1.D8(PC06) ; port ENET.RXD1
SPI2_CS: U1.C4(PC14) ; port SPI2.CS
SPI5_CS: U1.L7(PA26) ; port SPI5.CS
SPI5_MISO: U1.L6(PA24) ; port SPI5.MISO
SPI5_MOSI: U1.L8(PA27) ; port SPI5.MOSI
SPI5_SCK: U1.M7(PA25) ; port SPI5.SCLK
SWCLK: R12.1 ; port SWCLK
SWDIO: R11.1 ; port SWDIO
TXD0: U1.A3(PC12) ; port ENET.TXD0
TXDI: U1.A2(PC13) ; port ENET.TXD1
TXEN: U1.A4(PC11) ; port ENET.TXEN
UART0_CTS: U1.J2(PD12) ; port UART0.CTS
UART6_RX: U1.L3(PA01) ; port UART6.RX
UART6_TX: U1.L2(PA00) ; port UART6.TX
USB_D_N: U1.B1(USB0PN) ; port USB_HS.D_N
USB_D_P: U1.C1(USB0PP) ; port USB_HS.D_P
USBFS_D_N: U1.G1(USB_DM) ; port USB_FS.D_N
USBFS_D_P: U1.H1(USB_DP) ; port USB_FS.D_P
NetC3_2: C3.2 C4.2 C5.2 L1.2 U1.H7(AVDD)
NetC20_1: C20.1 U1.E1(PD00) Y1.3
NetC25_1: C25.1 U1.F1(PD01) Y1.1
NetC30_2: U1.D1(VBUS) ; port VBUS
NetJ2_3: U1.H12(PB04) ; port I2C4.SDA
NetJ2_4: U1.G8(PB05) ; port I2C4.SCL
NetJ3_6: U1.C6(PC21) ; port SPI2.MOSI
NetJ3_8: U1.C5(PC23) ; port SPI2.MISO
NetJ3_10: U1.C7(PC22) ; port SPI2.SCLK
NetJ3_14: U1.E10(PB21) ; port I2C3.SDA
NetJ3_16: U1.C9(PB22) ; port I2C3.SCL
NetJ3_18: U1.C3(PD14) ; port I2S.CK
NetJ3_20: U1.E3(PD13) ; port I2S.WS
NetJ3_22: U1.E2(PD16) ; port I2S.SDI
NetJ3_24: U1.F2(PD17) ; port I2S.SDO
NetJ3_28: U1.H3(PD08) ; port UART1.TX
NetJ3_30: U1.J4(PD09) ; port UART1.RX
NetR5_1: U1.A8(PC15) ; port PC15_TCC1_WO0
NetR7_1: U1.A6(PC17) ; port PC17_TCC1_WO2
NetR11_2: R11.2 U1.K3(PA02)
NetR12_2: R12.2 U1.K4(PA03)
NetR13_1: R13.1 U1.D2(USBRBIAS)
NetR18_2: U1.D11(PC00) ; port PC00_D11
NetR29_2: U1.B8(PC09) ; port ENET.RXER
NetR36_1: U1.L1(PD07) ; port UART0.RX
NetR37_2: U1.K1(PD05) ; port UART0.RTS
NetR38_2: U1.B6(PC16) ; port PC16_TCC1_WO1
NetU1_E11: U1.E11(PB08) ; port CAN0.CAN_TX
NetU1_E12: U1.E12(PB09) ; port CAN0.CAN_RX
NetU1_K2: U1.K2(PD06) ; port UART0.TX

Not connected (* = marked no-connect by the designer): U1 A5(PC18)* A7(PC28)* A9(PC27)* A10(PC26)* A11(PC24)* B7(PC29)* B9(PC05) B10(PC25)* C2(USBID)* C11(PC01)* D3(PD02)* D10(PB23)* D12(PB10)* F3(PD15)* F11(PB17)* F12(PB07)* G2(PD19)* G3(PD18)* G10(PB13)* G11(PB25)* G12(PB26)* H2(PD20)* H8(PB18)* H9(PB06)* H10(PB19)* H11(PB03)* J1(PD21)* J5(PD10)* J6(PA16)* J11(PB02)* J12(PB20)* K6(PA15)* K7(PA04)* K8(PA08)* K10(PB00)* L5(PA13)* L9(PA28)* L10(PA19)* M3(PA22)* M5(PA14)* M6(PA17)* M11(PA18)*; Y1 2(NC)* 4(NC)*

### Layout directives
differential pair; differential pair class USB: USB_D_N, USB_D_P
differential pair; differential pair class USBC_FS: USBFS_D_N, USBFS_D_P

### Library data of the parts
C3 C26 = C0195-A.3: as C12 on sheet TOP
C4 C7 C8 C13 C14 C23 C27 C29 = C0113-A.8: as C1 on sheet TOP
C5 C10 C11 C17 C18 C24 = C0205-A.3: as C9 on sheet TOP
C6 C21 = C0157-A.5: CAP CHIP 0402 22uF 20% 6.3V X5R; Manufacturer: Murata Electronics; Code Arduino: C0157
C20 C25 = C0144-A.5: CAP CHIP 0201 10pF 5% 50V C0G; Manufacturer: Yageo; Code Arduino: C0144
L1 = I0028-A.10: FERRITE SMD 0402 120Ohm 25% 100MHz Ferrite 2A; Manufacturer: Murata; Value: 120µH; DC Resistance (DCR): 55mR; Code Arduino: I0028
R11 R12 = R0228-A.17: RES CHIP 0201 22R 1% 1/20W; Manufacturer: Yageo; Code Arduino: R0228; Temperature coefficient: 200ppm; Power: 50mW
R13 = R0407-A.2: RES CHIP 0201 270R 1% 1/20W; Manufacturer: YAGEO; Temperature Coefficient: 200ppm; Code Arduino: R0407; Power: 50mW
U1 = U0591-A.1: IC Arm Cortex-M33 MCU with 2 MB Flash/512 KB SRAM 144-Pin -40° to 125° TFBGA; Manufacturer: Microchip Technology; Code Arduino: U0591
Y1 = X0038-A.1: CRYSTAL 12MHz 10pF SMD 2.5 x 2mm; Manufacturer: YXC Crystal Oscillators; Frequency Tolerance: 10ppm; Code Arduino: X0038; Frequency Stability: 20ppm

## Sheet CAN_PHY.SchDoc: CAN_PHY
size A4; SheetNumber: 3; SheetTotal: 5
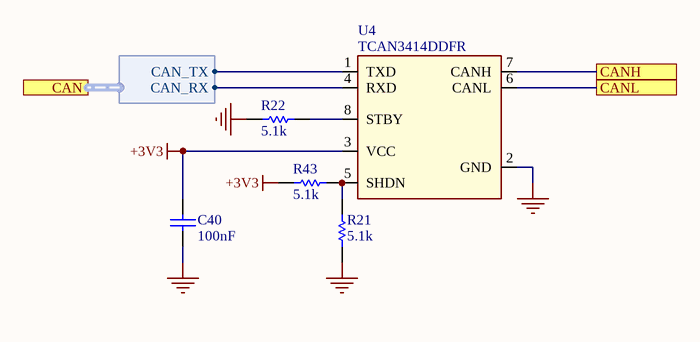
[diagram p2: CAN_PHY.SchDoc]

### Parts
C40  value 100nF  [CAP-0201]  (hidden comment: CL03A104KP3NNNC)
R21  value 5.1k  [RES-0201]  (hidden comment: RC0201FR-075K1L)
R22  value 5.1k  [RES-0201]  (hidden comment: RC0201FR-075K1L)
R43  value 5.1k  [RES-0201]  (hidden comment: RC0201FR-075K1L)
U4  TCAN3414DDFR  [SOT-23 Thin 8 pin 2.9 x 2.8mm]

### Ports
CAN (harness CAN_3V3), CANH, CANL

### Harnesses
CAN_3V3: CAN_TX, CAN_RX

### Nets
+3V3: C40.2 R43.1 U4.3(VCC)
GND: C40.1 R21.2 R22.2 U4.2(GND)
CANH: U4.7(CANH) ; port CANH
CANL: U4.6(CANL) ; port CANL
NetR21_1: R21.1 R43.2 U4.5(SHDN)
NetR22_1: R22.1 U4.8(STBY)
NetU1_E11: U4.1(TXD) ; port CAN.CAN_TX
NetU1_E12: U4.4(RXD) ; port CAN.CAN_RX

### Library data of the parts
C40 = C0113-A.8: as C1 on sheet TOP
R21 R22 R43 = R0169-A.26: as R1 on sheet TOP
U4 = U0540-A.4: IC CAN FD PHY up to 8Mbps, 3V3 VCC, Shut Down mode, Undervoltage protection, SOT-23 2.9 x 2.8mm; Manufacturer: Texas Instruments; Code Arduino: U0540

## Sheet ETH_10_100.SchDoc: ETH_10_100
size A4; SheetNumber: 4; SheetTotal: 5
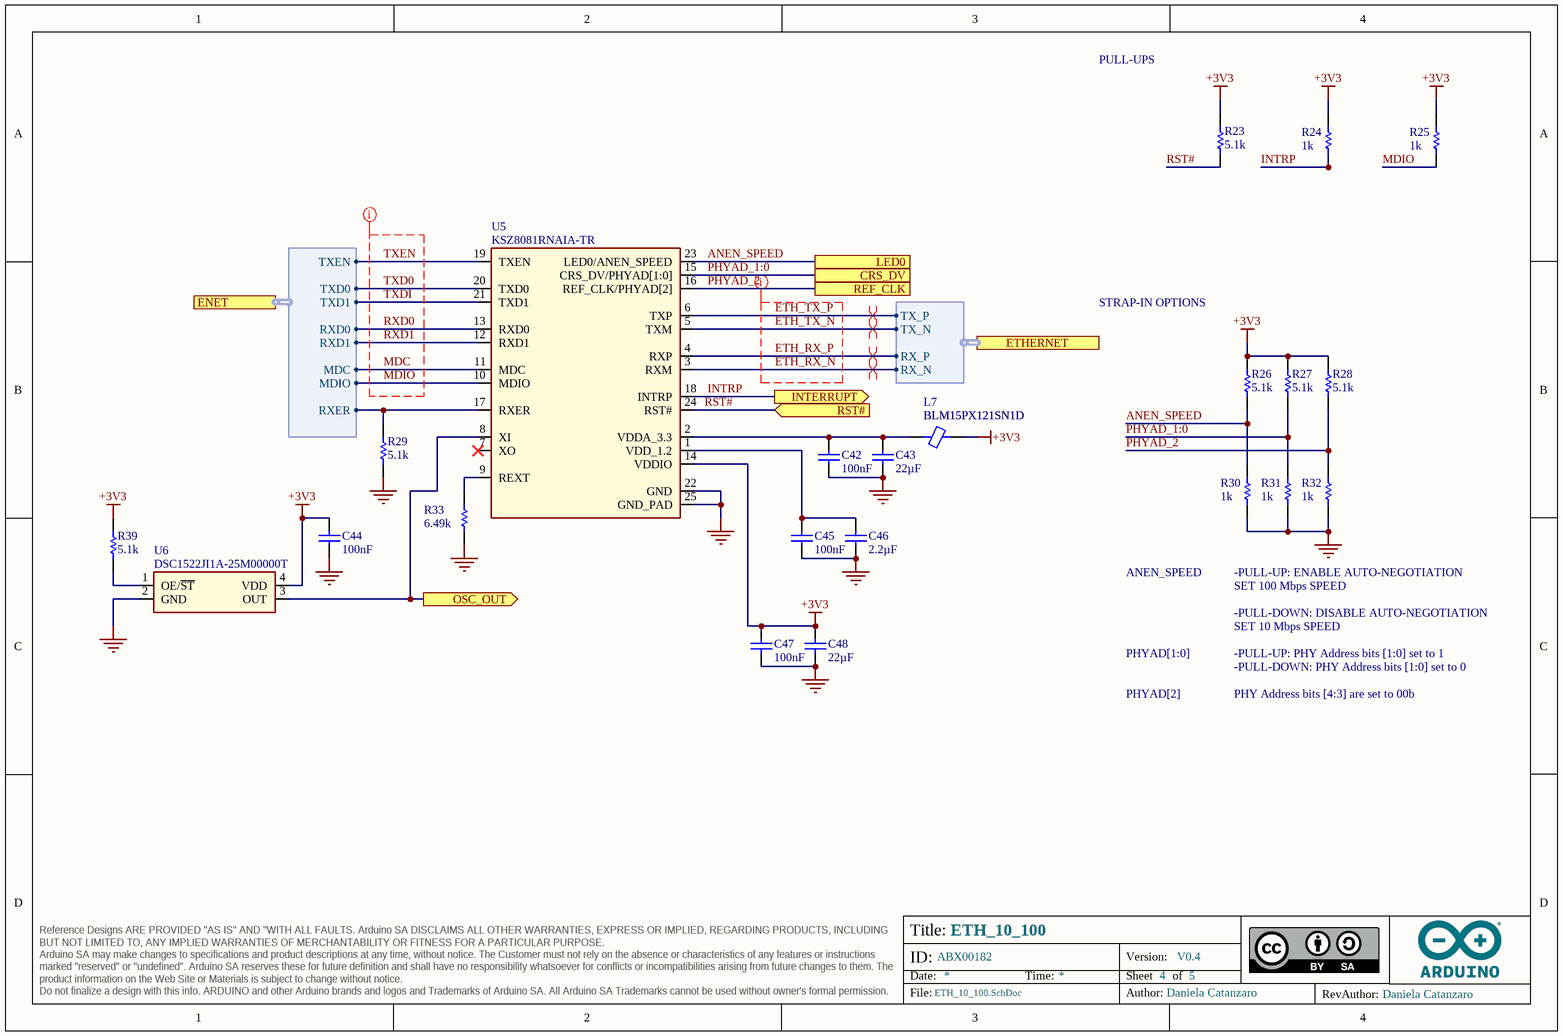
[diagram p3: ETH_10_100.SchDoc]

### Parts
C42  value 100nF  [CAP-0201]  (hidden comment: CL03A104KP3NNNC)
C43  value 22µF  [CAP-0402]  (hidden comment: GRM158R60J226ME01D)
C44  value 100nF  [CAP-0201]  (hidden comment: CL03A104KP3NNNC)
C45  value 100nF  [CAP-0201]  (hidden comment: CL03A104KP3NNNC)
C46  value 2.2µF  [CAP-0201]  (hidden comment: CM03X5R225M06AH)
C47  value 100nF  [CAP-0201]  (hidden comment: CL03A104KP3NNNC)
C48  value 22µF  [CAP-0402]  (hidden comment: GRM158R60J226ME01D)
L7  BLM15PX121SN1D  [L-0402]
R23  value 5.1k  [RES-0201]  (hidden comment: RC0201FR-075K1L)
R24  value 1k  [RES-0201]  (hidden comment: RC0201FR-071KL)
R25  value 1k  [RES-0201]  (hidden comment: RC0201FR-071KL)
R26  value 5.1k  [RES-0201]  (hidden comment: RC0201FR-075K1L)
R27  value 5.1k  [RES-0201]  (hidden comment: RC0201FR-075K1L)
R28  value 5.1k  [RES-0201]  (hidden comment: RC0201FR-075K1L)
R29  value 5.1k  [RES-0201]  (hidden comment: RC0201FR-075K1L)
R30  value 1k  [RES-0201]  (hidden comment: RC0201FR-071KL)
R31  value 1k  [RES-0201]  (hidden comment: RC0201FR-071KL)
R32  value 1k  [RES-0201]  (hidden comment: RC0201FR-071KL)
R33  value 6.49k  [RES-0201]  (hidden comment: RC0201FR-076K49L)
R39  value 5.1k  [RES-0201]  (hidden comment: RC0201FR-075K1L)
U5  KSZ8081RNAIA-TR  [QFN24 TP 2.6mmx2.6mm]
U6  DSC1522JI1A-25M00000T  [4-VLGA]

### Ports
CRS_DV, ENET (harness ENET), ETHERNET (harness ETH), INTERRUPT (out), LED0, OSC_OUT (out), REF_CLK, RST# (in)

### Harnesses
ETH: TX_N, TX_P, RX_N, RX_P
ENET: TXEN, TXD0, TXD1, RXD0, RXD1, MDC, MDIO, RXER

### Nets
+3V3: C44.2 C47.2 C48.2 L7.2 R23.2 R24.1 R25.1 R26.2 R27.2 R28.2 R39.2 U5.14(VDDIO) U6.4(VDD)
GND: C42.1 C43.1 C44.1 C45.1 C46.1 C47.1 C48.1 R29.1 R30.2 R31.2 R32.2 R33.1 U5.22(GND) U5.25(GND_PAD) U6.2(GND)
ANEN_SPEED: R26.1 R30.1 U5.23(LED0/ANEN_SPEED) ; port LED0
ETH_RX_N: U5.3(RXM) ; port ETHERNET.RX_N
ETH_RX_P: U5.4(RXP) ; port ETHERNET.RX_P
ETH_TX_N: U5.5(TXM) ; port ETHERNET.TX_N
ETH_TX_P: U5.6(TXP) ; port ETHERNET.TX_P
INTRP: R24.2 U5.18(INTRP) ; port INTERRUPT
MDC: U5.11(MDC) ; port ENET.MDC
MDIO: R25.2 U5.10(MDIO) ; port ENET.MDIO
PHYAD_1:0: R27.1 R31.1 U5.15(CRS_DV/PHYAD[1:0]) ; port CRS_DV
PHYAD_2: R28.1 R32.1 U5.16(REF_CLK/PHYAD[2]) ; port REF_CLK
RST#: R23.1 U5.24(RST#) ; port RST#
RXD0: U5.13(RXD0) ; port ENET.RXD0
RXD1: U5.12(RXD1) ; port ENET.RXD1
TXD0: U5.20(TXD0) ; port ENET.TXD0
TXDI: U5.21(TXD1) ; port ENET.TXD1
TXEN: U5.19(TXEN) ; port ENET.TXEN
NetC42_2: C42.2 C43.2 L7.1 U5.2(VDDA_3.3)
NetC45_2: C45.2 C46.2 U5.1(VDD_1.2)
NetR18_1: U5.8(XI) U6.3(OUT) ; port OSC_OUT
NetR29_2: R29.2 U5.17(RXER) ; port ENET.RXER
NetR33_2: R33.2 U5.9(REXT)
NetR39_1: R39.1 U6.1(OE/~{ST})

Not connected (* = marked no-connect by the designer): U5 7(XO)*

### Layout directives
net class RMII: MDC, MDIO, RXD0, RXD1, TXD0, TXDI, TXEN
net class ETH: ETH_RX_N, ETH_RX_P, ETH_TX_N, ETH_TX_P
differential pair; differential pair class ETH: ETH_RX_N, ETH_RX_P, ETH_TX_N, ETH_TX_P

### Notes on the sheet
- PULL-UPS
- STRAP-IN OPTIONS
- ANEN_SPEED
- -PULL-UP: ENABLE AUTO-NEGOTIATION
- SET 100 Mbps SPEED
- PHYAD[1:0]
- -PULL-DOWN: DISABLE AUTO-NEGOTIATION
- -PULL-UP: PHY Address bits [1:0] set to 1
- SET 10 Mbps SPEED
- PHYAD[2]
- -PULL-DOWN: PHY Address bits [1:0] set to 0
- PHY Address bits [4:3] are set to 00b

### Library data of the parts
C42 C44 C45 C47 = C0113-A.8: as C1 on sheet TOP
C43 C48 = C0157-A.5: as C6 on sheet MICROCONTROLLER
C46 = C0143-A.4: CAP CHIP 0201 2.2uF 20% 6V3 X5R; Manufacturer: KYOCERA AVX; Voltage: 6.3V; Code Arduino: C0143
L7 = I0028-A.10: as L1 on sheet MICROCONTROLLER
R23 R26-R29 R39 = R0169-A.26: as R1 on sheet TOP
R24 R25 R30-R32 = R0195-A.23: as R14 on sheet TOP
R33 = R0410-A.2: RES CHIP 0201 6.49k 1% 1/20W; Manufacturer: YAGEO; Code Arduino: R0410; Power: 50mW; Temperature Coefficient: 200
U5 = U0588-A.1: IC 10BASE-T/100BASE-TX PHY with RMII 25MHz mode default (Temp: –40C to +85C); Manufacturer: Microchip; Code Arduino: U0588; Max Temp: +85; Min Temp: -40
U6 = X0034-A.2: IC MEMS OSC 25MHz 50PPM VDD 2.25V - 3.63V  25MHz 2.5 mm x 2.0 mm 4-Lead VLGA; Manufacturer: Microchip Technology; Code Arduino: X0034; Max Supply Current: 7.5mA

## Sheet UART - RS485.SchDoc: UART - RS485
size A4; SheetNumber: 5; SheetTotal: 5
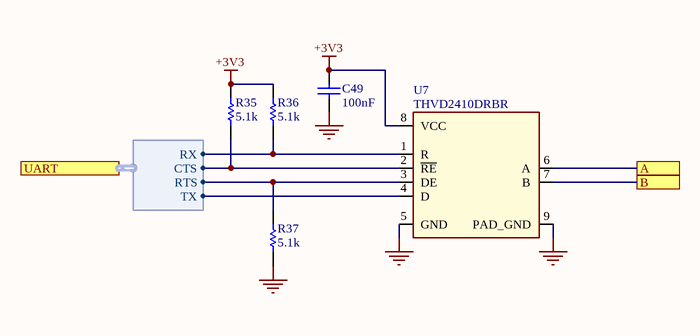
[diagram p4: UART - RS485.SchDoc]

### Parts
C49  value 100nF  [CAP-0201]  (hidden comment: CL03A104KP3NNNC)
R35  value 5.1k  [RES-0201]  (hidden comment: RC0201FR-075K1L)
R36  value 5.1k  [RES-0201]  (hidden comment: RC0201FR-075K1L)
R37  value 5.1k  [RES-0201]  (hidden comment: RC0201FR-075K1L)
U7  THVD2410DRBR  [DRB0008B]

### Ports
A, B, UART (harness UART)

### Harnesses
UART: CTS, RX, RTS, TX

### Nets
+3V3: C49.2 R35.2 R36.2 U7.8(VCC)
GND: C49.1 R37.1 U7.5(GND) U7.9(PAD_GND)
RS485 A: U7.6(A) ; port A
RS485 B: U7.7(B) ; port B
UART0_CTS: R35.1 U7.2(~{RE}) ; port UART.CTS
NetR36_1: R36.1 U7.1(R) ; port UART.RX
NetR37_2: R37.2 U7.3(DE) ; port UART.RTS
NetU1_K2: U7.4(D) ; port UART.TX

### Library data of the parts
C49 = C0113-A.8: as C1 on sheet TOP
R35-R37 = R0169-A.26: as R1 on sheet TOP
U7 = U0544-A.2: IC RS-485 Transceiver ±70-V Fault-Protected 3.3-V to 5-V 500kbps VSON 3mm x 3 mm; Manufacturer: Texas Instruments; Code Arduino: U0544

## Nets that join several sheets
+3V3: TOP (15 pins), MICROCONTROLLER (32 pins), CAN_PHY (C40.2 R43.1 U4.3), ETH_10_100 (13 pins), UART - RS485 (C49.2 R35.2 R36.2 U7.8)
GND: TOP (43 pins), MICROCONTROLLER (35 pins), CAN_PHY (C40.1 R21.2 R22.2 U4.2), ETH_10_100 (15 pins), UART - RS485 (C49.1 R37.1 U7.5 U7.9)
A0: TOP (J3.7), MICROCONTROLLER (U1.J10)
A1: TOP (J3.9), MICROCONTROLLER (U1.M8)
A2: TOP (J3.11), MICROCONTROLLER (U1.M9)
A3: TOP (J3.13), MICROCONTROLLER (U1.M10)
A4: TOP (J3.15), MICROCONTROLLER (U1.K11)
A5: TOP (J3.17), MICROCONTROLLER (U1.K12)
A6: TOP (J3.19), MICROCONTROLLER (U1.L12)
A7: TOP (J3.21), MICROCONTROLLER (U1.L11)
ANEN_SPEED: TOP (J4.19), ETH_10_100 (R26.1 R30.1 U5.23)
AREF: TOP (J3.5), MICROCONTROLLER (U1.K9)
CANH: TOP (J4.23 R8.2), CAN_PHY (U4.7)
CANL: TOP (J4.25 SJ1.1), CAN_PHY (U4.6)
ETH_RX_N: TOP (J4.15), ETH_10_100 (U5.3)
ETH_RX_P: TOP (J4.13), ETH_10_100 (U5.4)
ETH_TX_N: TOP (J4.9), ETH_10_100 (U5.5)
ETH_TX_P: TOP (J4.7), ETH_10_100 (U5.6)
INTRP: MICROCONTROLLER (U1.G9), ETH_10_100 (R24.2 U5.18)
MDC: MICROCONTROLLER (U1.B12), ETH_10_100 (U5.11)
MDIO: MICROCONTROLLER (U1.B11), ETH_10_100 (R25.2 U5.10)
NetC30_2: TOP (5 pins), MICROCONTROLLER (U1.D1)
NetJ2_3: TOP (J2.3 R40.1), MICROCONTROLLER (U1.H12)
NetJ2_4: TOP (J2.4 R20.1), MICROCONTROLLER (U1.G8)
NetJ3_6: TOP (J3.6), MICROCONTROLLER (U1.C6)
NetJ3_8: TOP (J3.8), MICROCONTROLLER (U1.C5)
NetJ3_10: TOP (J3.10), MICROCONTROLLER (U1.C7)
NetJ3_14: TOP (J3.14), MICROCONTROLLER (U1.E10)
NetJ3_16: TOP (J3.16), MICROCONTROLLER (U1.C9)
NetJ3_18: TOP (J3.18), MICROCONTROLLER (U1.C3)
NetJ3_20: TOP (J3.20), MICROCONTROLLER (U1.E3)
NetJ3_22: TOP (J3.22), MICROCONTROLLER (U1.E2)
NetJ3_24: TOP (J3.24), MICROCONTROLLER (U1.F2)
NetJ3_28: TOP (J3.28), MICROCONTROLLER (U1.H3)
NetJ3_30: TOP (J3.30), MICROCONTROLLER (U1.J4)
NetR5_1: TOP (R5.1), MICROCONTROLLER (U1.A8)
NetR7_1: TOP (R7.1), MICROCONTROLLER (U1.A6)
NetR18_1: TOP (R18.1), ETH_10_100 (U5.8 U6.3)
NetR18_2: TOP (R18.2 R19.2), MICROCONTROLLER (U1.D11)
NetR29_2: MICROCONTROLLER (U1.B8), ETH_10_100 (R29.2 U5.17)
NetR36_1: MICROCONTROLLER (U1.L1), UART - RS485 (R36.1 U7.1)
NetR37_2: MICROCONTROLLER (U1.K1), UART - RS485 (R37.2 U7.3)
NetR38_2: TOP (R38.2), MICROCONTROLLER (U1.B6)
NetU1_E11: MICROCONTROLLER (U1.E11), CAN_PHY (U4.1)
NetU1_E12: MICROCONTROLLER (U1.E12), CAN_PHY (U4.4)
NetU1_K2: MICROCONTROLLER (U1.K2), UART - RS485 (U7.4)
PA20_TCC4_WO0: TOP (J4.16), MICROCONTROLLER (U1.K5)
PA21_TCC4_WO1: TOP (J4.18), MICROCONTROLLER (U1.M2)
PA23_TCC5_WO1: TOP (J4.10), MICROCONTROLLER (U1.M4)
PB11_TCC3_WO6: TOP (J4.14), MICROCONTROLLER (U1.J9)
PB16_GPIO: TOP (R3.2), MICROCONTROLLER (U1.C10)
PB24_TCC6_WO1: TOP (J4.8), MICROCONTROLLER (U1.C8)
PC02_GPIO: TOP (R44.2 R46.1), MICROCONTROLLER (U1.C12)
PC19_TCC1_WO4: TOP (J4.22), MICROCONTROLLER (U1.B3)
PC20_TCC1_WO5: TOP (J4.20), MICROCONTROLLER (U1.B4)
PD11_TCC2_WO2: TOP (J4.12), MICROCONTROLLER (U1.J3)
PHYAD_1:0: MICROCONTROLLER (U1.B5), ETH_10_100 (R27.1 R31.1 U5.15)
PHYAD_2: TOP (R19.1), ETH_10_100 (R28.1 R32.1 U5.16)
~{RESET}: TOP (5 pins), MICROCONTROLLER (U1.L4)
RS485 A: TOP (J4.27 R34.2), UART - RS485 (U7.6)
RS485 B: TOP (J4.29 SJ2.1), UART - RS485 (U7.7)
RST#: MICROCONTROLLER (U1.F10), ETH_10_100 (R23.1 U5.24)
RXD0: MICROCONTROLLER (U1.D7), ETH_10_100 (U5.13)
RXD1: MICROCONTROLLER (U1.D8), ETH_10_100 (U5.12)
SPI2_CS: TOP (J3.12), MICROCONTROLLER (U1.C4)
SPI5_CS: TOP (J4.6), MICROCONTROLLER (U1.L7)
SPI5_MISO: TOP (J4.2), MICROCONTROLLER (U1.L6)
SPI5_MOSI: TOP (J4.4), MICROCONTROLLER (U1.L8)
SPI5_SCK: TOP (J3.1), MICROCONTROLLER (U1.M7)
SWCLK: TOP (GPIO1.X J3.26), MICROCONTROLLER (R12.1)
SWDIO: TOP (J3.25 NC1.X), MICROCONTROLLER (R11.1)
TXD0: MICROCONTROLLER (U1.A3), ETH_10_100 (U5.20)
TXDI: MICROCONTROLLER (U1.A2), ETH_10_100 (U5.21)
TXEN: MICROCONTROLLER (U1.A4), ETH_10_100 (U5.19)
UART0_CTS: MICROCONTROLLER (U1.J2), UART - RS485 (R35.1 U7.2)
UART6_RX: TOP (J4.28), MICROCONTROLLER (U1.L3)
UART6_TX: TOP (J4.30), MICROCONTROLLER (U1.L2)
USB_D_N: TOP (5 pins), MICROCONTROLLER (U1.B1)
USB_D_P: TOP (5 pins), MICROCONTROLLER (U1.C1)
USBFS_D_N: TOP (J3.4), MICROCONTROLLER (U1.G1)
USBFS_D_P: TOP (J3.2), MICROCONTROLLER (U1.H1)

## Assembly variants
ABX00182: not fitted C1 R18 R27 R28 R30 R44 R?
